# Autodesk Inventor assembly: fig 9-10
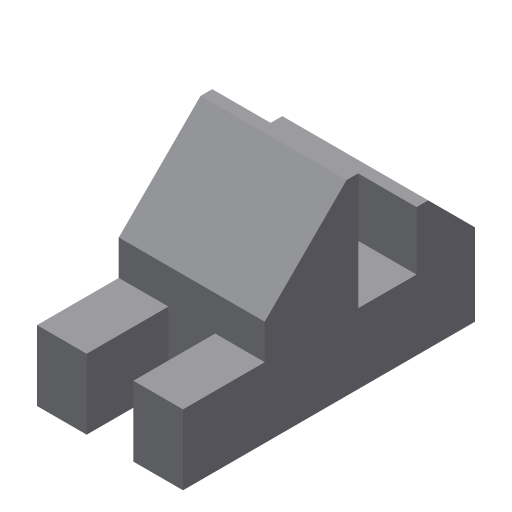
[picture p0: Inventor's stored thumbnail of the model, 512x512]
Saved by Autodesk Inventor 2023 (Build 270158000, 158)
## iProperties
Created: 2002-01
Part Number: fig 9-10
Document SubType Name: Assembly
Designer: ***
Control State: 0
Master: False
Checked Out: False
Shininess: 64.0
Length Units: 11269
Angle Units: 11279
Time Units: 11290
Mass Units: 11283
Length Display Precision: 3
Angle Display Precision: 2
Density: 0.0
Volumn: 0.0
Area: 0.0
PropertySet Name: Model Information
Author: ***
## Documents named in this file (3)
- D:\PROJECTS\Project 2022\Autodesk Inventor For Professional 2023\RESOURCES INVENTOR 2023\RESOURCES INVENTOR 2023\Inventor_2023_Part\Inventor_2023_Part\c09_Inv_2023_prt\fig 9-10.iam
- D:\PROJECTS\Project 2022\Autodesk Inventor For Professional 2023\RESOURCES INVENTOR 2023\RESOURCES INVENTOR 2023\Inventor_2023_Part\Inventor_2023_Part\c09_Inv_2023_prt\Part3.ipt
- D:\PROJECTS\Project 2022\Autodesk Inventor For Professional 2023\RESOURCES INVENTOR 2023\RESOURCES INVENTOR 2023\Inventor_2023_Part\Inventor_2023_Part\c09_Inv_2023_prt\Part4.ipt
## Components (2 placed, 2 different names)
1. Part3:1
2. Part4:1
